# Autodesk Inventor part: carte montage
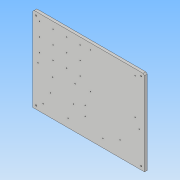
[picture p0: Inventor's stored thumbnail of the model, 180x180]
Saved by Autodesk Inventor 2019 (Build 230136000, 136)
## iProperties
Created: 2024-07
Part Number: carte montage
Material: Générique
Document SubType Name: Modeling
Designer: admin
Density: 1 g/cm^3
Appearance: Par défaut
Author: admin
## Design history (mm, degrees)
sketch "Esquisse1"
  geometry: L1 (-165, 125)-(165, 125); L2 (165, 125)-(165, -125); L3 (165, -125)-(-165, -125); L4 (-165, -125)-(-165, 125); 1 further point
  constraints: 8 end point, 2 parallel, 1 horizontal, 1 perpendicular
  dimensions: "d0" = 250 distance of L3.end L1.start; "d1" = 330 distance of L1.start L1.end; "d2" = 165 distance from line of point (0, 0) L4 (= 0.5 x d1); "d3" = 125 distance from line of point (0, 0) L1 (= 0.5 x d0)
extrude "Extrusion1" new body sketch "Esquisse1" distance "d4" = 8; taper "d5" = 0 deg
sketch "Esquisse2"
  geometry: L1 (-155, 115)-(155, 115); L2 (155, 115)-(155, -115); L3 (155, -115)-(-155, -115); L4 (-155, -115)-(-155, 115); L5 (165, -125)-(165, 125) reference; L6 (165, 125)-(-165, 125) reference; L7 (-165, 125)-(-165, -125) reference; L8 (-165, -125)-(165, -125) reference; 5 further points
  constraints: 8 end point, 4 coincident, 2 parallel, 1 horizontal, 1 perpendicular
  dimensions: "d6" = 10 distance between parallel lines of L5 L2; "d7" = 10 distance between parallel lines of L6 L1; "d8" = 10 distance between parallel lines of L7 L4; "d9" = 10 distance between parallel lines of L8 L3
hole "Perçage1" sketch "Esquisse2" at (-155, 115), (155, 115), (155, -115), (-155, -115) diameter "d10" = 4.134; stored, may be unused: countersink angle "d14" = 90 deg, drill point angle "d16" = 118 deg; dims "d11" = 10, "d12" = 4, "d13" = 2, "d15" = 14.2
chamfer "Chanfrein1" distance "d17" = 4; stored, may be unused: second distance "d18" = 2, angle "d19" = 45 deg
sketch "Esquisse3"
  geometry: L1 (-165, 121)-(-165, -125); L2 (-165, -125)-(165, -125); L3 (-165, 121)-(-161, 125); L4 (161, 125)-(-161, 125); L5 (161, 125)-(165, 121); L6 (165, -125)-(165, 121); L7 (-165, -125)-(165, -125) reference; L8 (165, -125)-(165, 121) reference; C1 r 1.6 at (-112.836, -61.82); C2 r 1.6 at (-60.766, -100.936); C3 r 1.6 at (-106.486, -18.64); C4 r 1.6 at (-149.412, -3.146); C5 r 1.6 at (-44.51, -56.232); C6 r 1.6 at (-40.192, -1.876); C7 r 2.15 at (5.3, 0.7); C8 r 2.15 at (137.38, 0.7); C9 r 2.15 at (137.38, 107.38); C10 r 2.15 at (5.3, 107.38); C11 r 1.6 at (-9.973, -42.516); C12 r 1.6 at (-9.973, -70.456); C13 r 1.6 at (42.097, -100.936); C14 r 1.6 at (92.77, -79.346); C15 r 1.6 at (149.666, -23.593); C16 r 1.6 at (-134.426, -100.428); 17 further points
  constraints: 16 centre point, 16 coincident, 12 end point
  dimensions: "d20" = 250 distance between parallel lines of L4 L2; "d21" = 330 distance between parallel lines of L6 L1; "d22" = 4 horizontal distance of L3.end L1.start; "d23" = 4 horizontal distance of L3.end L1.start; "d24" = 4 distance from line of L6 L4.start; "d25" = 4 horizontal distance of L5.end L4.start; "d26" = 246 distance of L1.start L1.end; "d27" = 330 distance of L2.end L1.end; "d28" = 27.62 distance from line of L6 C9.centre; "d29" = 17.62 distance from line of L4 C9.centre; "d30" = 17.62 distance from line of L4 C10.centre; "d31" = 132.08 distance of C9.centre C10.centre; "d32" = 106.68 distance of C9.centre C8.centre; "d33" = 106.68 distance of C7.centre C10.centre; "d34" = 132.08 distance of C8.centre C7.centre; "d35" = 15.334 distance from line of L6 C15.centre; "d36" = 72.23 distance from line of L6 C14.centre; "d37" = 122.903 distance from line of L6 C13.centre; "d38" = 174.973 distance from line of L6 C11.centre; "d39" = 174.973 distance from line of L6 C12.centre; "d40" = 209.51 distance from line of L6 C5.centre; "d41" = 225.766 distance from line of L6 C2.centre; "d42" = 299.426 distance from line of L6 C16.centre; "d43" = 277.836 distance from line of L6 C1.centre; "d44" = 271.486 distance from line of L6 C3.centre; "d45" = 205.192 distance from line of L6 C6.centre; "d46" = 314.412 distance from line of L6 C4.centre; "d47" = 101.407 distance from line of L2 C15.centre; "d48" = 45.654 distance from line of L2 C14.centre; "d49" = 24.064 distance from line of L2 C13.centre; "d50" = 54.544 distance from line of L2 C12.centre; "d51" = 82.484 distance from line of L2 C11.centre; "d52" = 24.064 distance from line of L2 C2.centre; "d53" = 68.768 distance from line of L2 C5.centre; "d54" = 123.124 distance from line of L2 C6.centre; "d55" = 106.36 distance from line of L2 C3.centre; "d56" = 63.18 distance from line of L2 C1.centre; "d57" = 24.572 distance from line of L2 C16.centre; "d58" = 121.854 distance from line of L2 C4.centre; "d59" = 159.7 distance from line of L6 C10.centre (derived); "d60" = 159.7 distance from line of L6 C7.centre; "d61" = 27.62 distance from line of L6 C8.centre (derived); "d62" = 124.3 distance from line of L4 C7.centre (derived); "d63" = 124.3 distance from line of L4 C8.centre (derived)
hole "Perçage2" sketch "Esquisse3" at (5.3, 107.38), (137.38, 107.38), (137.38, 0.7), (5.3, 0.7), (-40.192, -1.876), (-149.412, -3.146), (-106.486, -18.64), (149.666, -23.593), (-9.973, -42.516), (-44.51, -56.232), (-112.836, -61.82), (-9.973, -70.456)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 diameter "d64" = 2.459; stored, may be unused: countersink angle "d68" = 90 deg, drill point angle "d70" = 118 deg; dims "d65" = 6, "d66" = 4, "d67" = 2, "d69" = 8.8
sketch "Esquisse4"
  geometry: L1 (-145, 105)-(-65, 105); L2 (-65, 105)-(-65, 25); L3 (-65, 25)-(-145, 25); L4 (-145, 25)-(-145, 105); L5 (-165, 121)-(-165, -125) reference; L6 (161, 125)-(-161, 125) reference; L7 (-145, 65)-(0, 65); L8 (-105, 105)-(-105, 25); L9 (-65, 105)-(-25, 105); L10 (-25, 105)-(-25, 25); L11 (-25, 25)-(-65, 25); L12 (-65, 25)-(-65, 105); 12 further points
  constraints: 20 end point, 9 coincident, 5 midpoint, 4 parallel, 3 horizontal, 2 perpendicular, 2 point on line
  dimensions: "d71" = 80 distance of L3.end L1.start; "d72" = 80 distance of L1.start L1.end; "d73" = 20 distance between parallel lines of L5 L4; "d74" = 20 distance between parallel lines of L6 L1; "d75" = 40 distance from line of L2 point (-25, 65)
hole "Perçage3" sketch "Esquisse4" at (-145, 105), (-105, 105), (-65, 105), (-145, 65), (-105, 65), (-65, 65), (-145, 25), (-105, 25), (-65, 25), (-25, 65), (-25, 105), (-25, 25) diameter "d76" = 2.459; stored, may be unused: countersink angle "d80" = 90 deg, drill point angle "d82" = 118 deg; dims "d77" = 6, "d78" = 4, "d79" = 2, "d81" = 8.8
node "Solide1"
